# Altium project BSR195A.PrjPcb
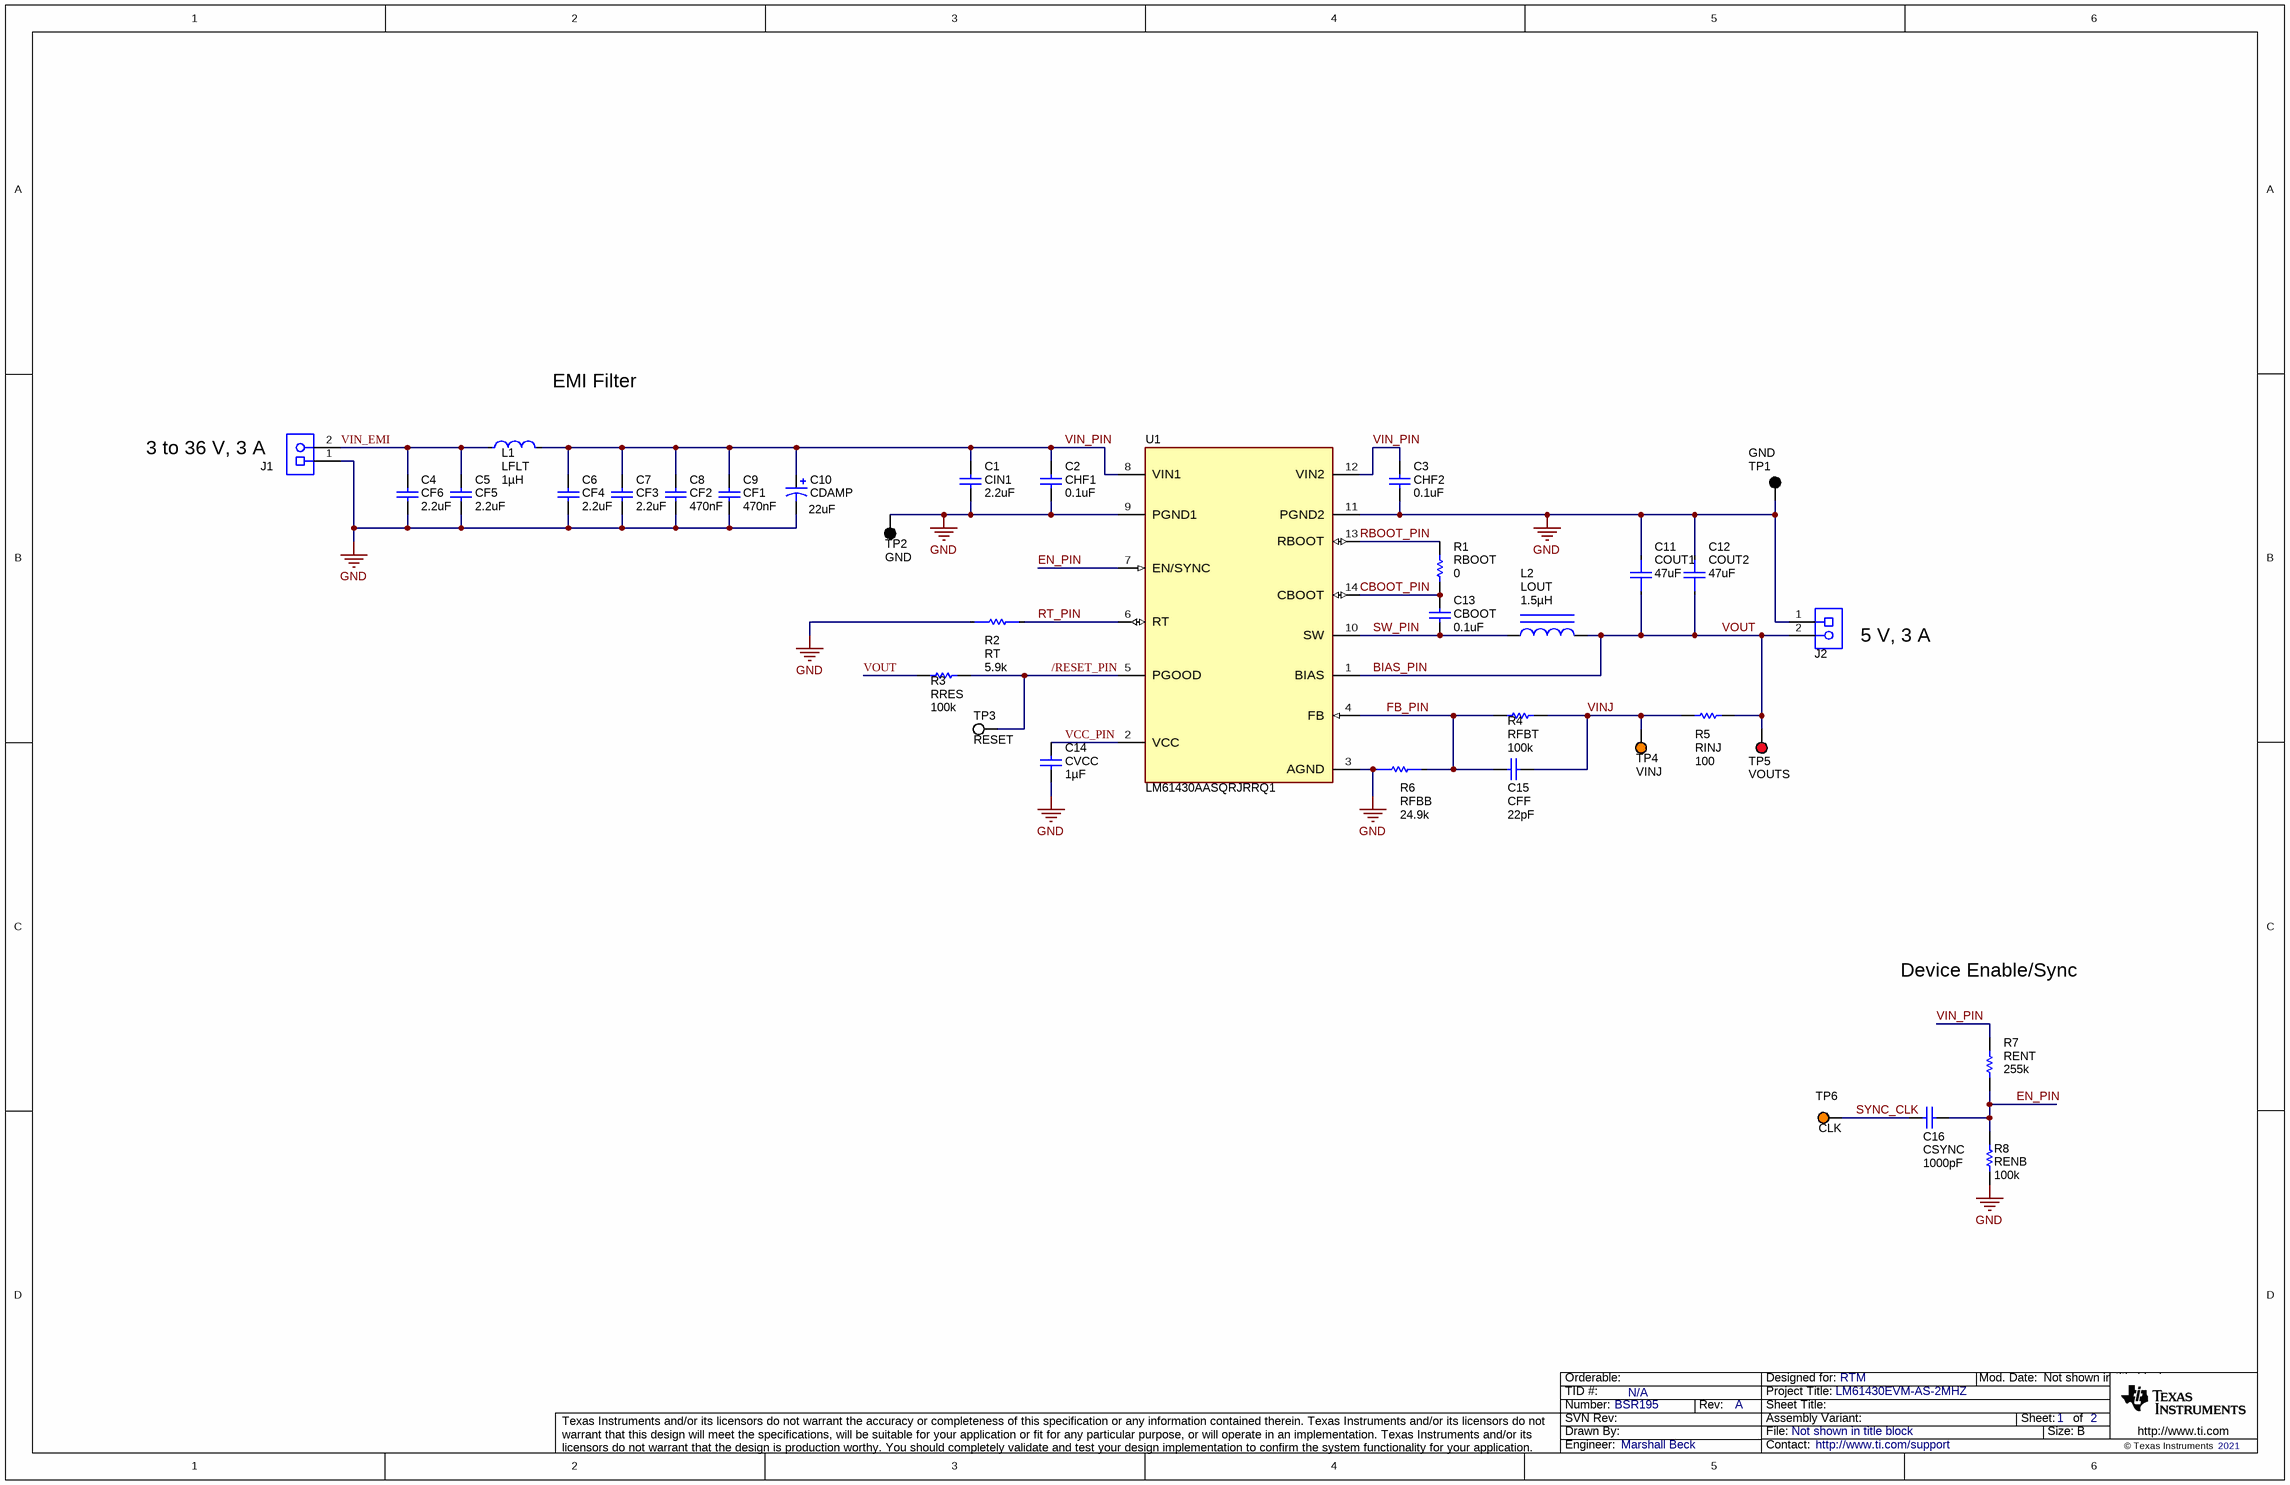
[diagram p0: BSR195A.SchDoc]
CopyrightYear: 2021; PCB_Layout: Marshall Beck; PCB_Rev: A; PRJ_Customer: RTM; PRJ_Engineer: Marshall Beck; PRJ_Number: BSR195; PRJ_Title: LM61430EVM-AS-2MHZ; SCH_Rev: A; TechSupport: http://www.ti.com/support; TID: N/A
2 sheets, 60 parts. Net scope: global (net labels, ports and power ports of the same name join across sheets).
Board file: BSR195A.PcbDoc
Sheets:
  BSR195A.SchDoc
  BSR195A_Hardware.SchDoc

## Sheet BSR195A.SchDoc
size 431 x 279 mm; Date: Not shown in title block; ApprovedBy: Not shown in title block; CheckedBy: Not shown in title block; Author: Not shown in title block; CompanyName: Not shown in title block; Engineer: Not shown in title block; Organization: Not shown in title block; Address1: Not shown in title block; Address2: Not shown in title block; Address3: Not shown in title block; Address4: Not shown in title block; DocumentNumber: 1; Revision: Use project parameter SCH_Rev; SheetNumber: 1; SheetTotal: 2; PageSetup: Record=PageOptions¦CenterHorizontal=True¦CenterVertical=True¦PrintScale=1.00¦XCorrection=1.00¦YCorrection=1.00¦PrintKind=0¦BorderSize=5000000¦LeftOffset=0¦BottomOffset=0¦Orientation=2¦PaperLength=1000¦PaperWidth=1000¦Scale=100¦PaperSource=15¦PrintQuality=600¦MediaType=1¦DitherType=10¦PaperKind=Letter¦PrintScaleMode=1

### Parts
C1  CIN1  ValueDisplayed: 2.2uF  [1206_180L]
C2  CHF1  ValueDisplayed: 0.1uF  [0402L]
C3  CHF2  ValueDisplayed: 0.1uF  [0402L]
C4  CF6  ValueDisplayed: 2.2uF  [1206_180L]
C5  CF5  ValueDisplayed: 2.2uF  [1206_180L]
C6  CF4  ValueDisplayed: 2.2uF  [1206_180L]
C7  CF3  ValueDisplayed: 2.2uF  [1206_180L]
C8  CF2  Cap_F: 470nF  [0805L]
C9  CF1  Cap_F: 470nF  [0805L]
C10  CDAMP  ValueDisplayed: 22uF  [SM_RADIAL_E]
C11  COUT1  ValueDisplayed: 47uF  [FP-CGA6P1X7S1A476M250AC_1210-MFG]
C12  COUT2  ValueDisplayed: 47uF  [FP-CGA6P1X7S1A476M250AC_1210-MFG]
C13  CBOOT  ValueDisplayed: 0.1uF  [0402L]
C14  CVCC  Cap_F: 1µF  [0603L]
C15  CFF  ValueDisplayed: 22pF  [0402L]
C16  CSYNC  ValueDisplayed: 1000pF  [0402L]
J1  691 101 710 002  [Wurth_691101710002]  (value not drawn)
J2  691 101 710 002  [Wurth_691101710002]  (value not drawn)
L1  LFLT  Ind_H: 1µH  [FP-74438336010_SMD2-MFG]
L2  LOUT  ValueDisplayed: 1.5µH  [WE-MAPI_4020]
R1  RBOOT  ValueDisplayed: 0  [0402L]
R2  RT  value 5.9k  [FP-ERJ-2RKF5901X_0402-IPC_B]
R3  RRES  ValueDisplayed: 100k  [0402L]
R4  RFBT  ValueDisplayed: 100k  [0402L]
R5  RINJ  ValueDisplayed: 100  [0603L]
R6  RFBB  value 24.9k  [FP-ERJ-2RKF2492X_0402-MFG]
R7  RENT  ValueDisplayed: 255k  [0402L]
R8  RENB  ValueDisplayed: 100k  [0402L]
TP1  GND  [Keystone5011]
TP2  GND  [Keystone5011]
TP3  RESET  [Keystone5012]
TP4  VINJ  [Keystone5013]
TP5  VOUTS  [Keystone5010]
TP6  CLK  [Keystone5013]
U1  LM61430AASQRJRRQ1  [RJR0014A-MFG]

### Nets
GND: C1.2 C2.2 C3.2 C4.2 C5.2 C6.2 C7.2 C8.2 C9.2 C10.2(-) C11.2 C12.2 C14.2 J1.1 J2.1 R2.1 R6.1 R8.1 TP1.1 TP2.1 U1.3(AGND) U1.9(PGND1) U1.11(PGND2)
/RESET_PIN: R3.2 TP3.1 U1.5(PGOOD)
BIAS_PIN: C11.1 C12.1 J2.2 L2.2 R3.1 R5.1 TP5.1 U1.1(BIAS)  [also labelled VOUT]
CBOOT_PIN: C13.1 R1.1 U1.14(CBOOT)
EN_PIN: C16.1 R7.1 R8.2 U1.7(EN/SYNC)
FB_PIN: C15.2 R4.1 R6.2 U1.4(FB)
RBOOT_PIN: R1.2 U1.13(RBOOT)
RT_PIN: R2.2 U1.6(RT)
SW_PIN: C13.2 L2.1 U1.10(SW)
SYNC_CLK: C16.2 TP6.1
VCC_PIN: C14.1 U1.2(VCC)
VIN_EMI: C4.1 C5.1 J1.2 L1.1
VIN_PIN: C1.1 C2.1 C3.1 C6.1 C7.1 C8.1 C9.1 C10.1(+) L1.2 R7.2 U1.8(VIN1) U1.12(VIN2)
VINJ: C15.1 R4.2 R5.2 TP4.1

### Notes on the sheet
- EMI Filter
- (near J1) 3 to 36 V, 3 A
- (near J2) 5 V, 3 A
- Device Enable/Sync

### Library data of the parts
C1 C4-C7 = CMP-0008814-2: CAP, CERM, 2.2 uF, 50 V, +/- 10%, X7R, AEC-Q200 Grade 1, 1206; Manufacturer: MuRata; PartNumber: GCM31CR71H225KA55L; TaMin_C: -55°C; Polarized: N; SizeAreaWB_mm2: 10.92; Value1: Unknown; U/M: EA; Value: 2.2uF; TaMax_C: 125°C; SizeZ_mm: 1.8; SizeX_mm: 3.2; SizeY_mm: 1.6; Cap_Case: 1206; Value2: 50V; SizeArea_mm2: 5.12; CompType: Capacitor; AEC Qualified: Y; Cap_F: 2.2µF; AEC Grade: 1; AEC Category: Q200
C2 C3 C13 = CMP-0006356-2: CAP, CERM, 0.1 uF, 50 V, +/- 10%, X7R, AEC-Q200 Grade 1, 0402; Manufacturer: MuRata; PartNumber: GCM155R71H104KE02D; TaMin_C: -55°C; Polarized: N; SizeAreaWB_mm2: 3; Value1: Unknown; U/M: EA; Value: 0.1uF; TaMax_C: 125°C; SizeZ_mm: 0.6; SizeX_mm: 1; SizeY_mm: 0.5; Cap_Case: 0402; Value2: 50V; CompType: Capacitor; AEC Qualified: Y; Cap_F: 100nF; AEC Category: Q200
C8 C9 = CMP-0008022-2: CAP, CERM, 0.47 uF, 50 V, +/- 10%, X7R, AEC-Q200 Grade 1, 0805; Manufacturer: MuRata; PartNumber: GCM21BR71H474KA55L; TaMin_C: -55°C; Polarized: N; SizeAreaWB_mm2: 6.75; Value1: Unknown; U/M: EA; Value: 0.47uF; TaMax_C: 125°C; SizeZ_mm: 1.45; SizeX_mm: 2; SizeY_mm: 1.25; Cap_Case: 0805; Value2: 50V; SizeArea_mm2: 2.5; CompType: Capacitor; AEC Qualified: Y; AEC Grade: 1; AEC Category: Q200
C10 = CMP-0011168-2: CAP, AL, 22 uF, 50 V, +/- 20%, 0.7 ohm, SMD; Manufacturer: Panasonic; PartNumber: EEE-FC1H220P; TaMin_C: -40°C; ESR_ohm: 7d; Polarized: Y; SizeAreaWB_mm2: 118.45; Value1: 0.7 ohm; U/M: EA; Value: 22uF; TaMax_C: 105°C; SizeZ_mm: 6.2; SizeX_mm: 9.5; SizeY_mm: 8.3; Cap_Case: E; Value2: 50V; SizeArea_mm2: 78.85; CompType: Capacitor; Cap_F: 22µF; IRMS_A: 1.2dA; AEC Category: Q200
C11 C12 = CMP-0092443-1: Multilayer Ceramic Capacitor 47uF 20% 10V 1210 T/R; PartNumber: CGA6P1X7S1A476M250AC; Manufacturer: TDK; AEC Grade: Grade 1; TempCo: 22%; Value: 47µF; AEC Qualified: Yes; Temperature Characteristic: X7S; SizeZ_mm: 2.8mm
C14 = CMP-0006831-4: CAP, CERM, 1 uF, 16 V, +/- 10%, X7R, 0603; Manufacturer: Wurth Elektronik; PartNumber: 885012206052; TaMin_C: -55°C; Polarized: N; SizeAreaWB_mm2: 4.68; Value1: Unknown; U/M: EA; Value: 1uF; TaMax_C: 125°C; SizeZ_mm: 1; SizeX_mm: 1.6; SizeY_mm: 0.8; Cap_Case: 0603; Value2: 16V; SizeArea_mm2: 1.28; CompType: Capacitor; AEC Category: Q200
C15 = CMP-0006311-2: CAP, CERM, 22 pF, 50 V, +/- 5%, C0G/NP0, AEC-Q200 Grade 1, 0402; Manufacturer: TDK; PartNumber: CGA2B2NP01H220J050BA; TaMin_C: -55°C; Polarized: N; SizeAreaWB_mm2: 3; Value1: Unknown; U/M: EA; Value: 22pF; TaMax_C: 125°C; SizeZ_mm: 0.6; SizeX_mm: 1; SizeY_mm: 0.5; Cap_Case: 0402; Value2: 50V; CompType: Capacitor; AEC Qualified: Y; AEC Category: Q200
C16 = CMP-0006314-2: CAP, CERM, 1000 pF, 50 V, +/- 10%, X7R, AEC-Q200 Grade 1, 0402; Manufacturer: TDK; PartNumber: CGA2B2X7R1H102K050BA; TaMin_C: -55°C; ESR_ohm: 2.25564; Polarized: N; SizeAreaWB_mm2: 3; Value1: 2.25564 ohm; U/M: EA; Value: 1000pF; TaMax_C: 125°C; SizeZ_mm: 0.6; SizeX_mm: 1; SizeY_mm: 0.5; Cap_Case: 0402; Value2: 50V; CompType: Capacitor; AEC Qualified: Y; Cap_F: 1nF; IRMS_A: 280.466mA; AEC Category: Q200
J1 J2 = CMP-0054828-1: Terminal Block, 5 mm, 2x1, Tin, TH; Manufacturer: Wurth Elektronik; CNHeader: FALSE; Green_Lifecycle: Active; Green_REACh: Passed; CT: TRUE
L1 = CMP-0087867-1: 1µH Shielded Molded Inductor 4A 32mOhm Max 2-SMD; Manufacturer: Wurth Electronics; PartNumber: 74438336010; SizeZ_mm: 2mm; Material: Metal Composite; Isat: 5A; Symbol Name: SYM-74438336010; DCR_ohm: 0.032; AEC Grade: Grade 1; AEC Qualified: Yes
L2 = CMP-0084012-1: Inductor, Shielded, Metal Composite, 1.5 µH, 5.8 A, 0.019 ohm, SMD; PartNumber: 74438356015; Manufacturer: Wurth Elektronik; SizeAreaWB_mm2: 26.01; Irms: 5.8A @ 40C rise; SizeArea_mm2: 16.81; AEC Qualified: N; AEC Category: Q200; Value: 1.5uH; SizeZ_mm: 2.1; Imax_A: 5.8A; SizeY_mm: 4.1; Isat: 7.8A @ 20% inductance drop; DCR_ohm: 0.019
R1 = CMP-0081856-1: RES, 0, 0%, 0.2 W, AEC-Q200 Grade 0, 0402; PartNumber: CRCW04020000Z0EDHP; Manufacturer: Vishay-Dale; SizeAreaWB_mm2: 3; SizeArea_mm2: 0.5; AEC Qualified: Y; AEC Category: Q200; Value: 0; SizeZ_mm: 0.6; Power_W: 200mW; VDC_V: 50V; Value2: 0.2W; CompType: Resistor; SizeX_mm: 1
R2 = CMP-0091636-1: 5.9 kOhms ±1% 0.1W, 1/10W Chip Resistor 0402 (1005 Metric) Automotive AEC-Q200 Thick Film; PartNumber: ERJ-2RKF5901X; Manufacturer: Panasonic; TempCo: 100ppm/°C; AEC Qualified: Yes; AEC Grade: Grade 0; VDC_V: 50V; Power_W: 100mW; SizeZ_mm: 0.4mm
R3 R4 R8 = CMP-0026768-2: RES, 100 k, 0.5%, 0.063 W, AEC-Q200 Grade 0, 0402; Manufacturer: Vishay-Dale; PartNumber: CRCW0402100KDHEDP; Power_W: 63mW; TempCo: 50 ppm/C; Value: 100k; EIA_Code: E192; SizeX_mm: 1; SizeY_mm: 0.5; SizeZ_mm: 0.6; Value2: 0.063W; CompType: Resistor; AEC Qualified: Y; VDC_V: 50V; AEC Category: Q200; AEC Grade: 0
R5 = CMP-0022736-4: RES, 100, 1%, 0.1 W, 0603; Manufacturer: Yageo; PartNumber: RC0603FR-07100RL; Power_W: 100mW; TempCo: 100 ppm/C; Value_Code: 100R; Value: 100; EIA_Code: E96; SizeX_mm: 1.6; SizeY_mm: 0.8; SizeZ_mm: 1; Value2: 0.1W; SizeArea_mm2: 1.28; CompType: Resistor; AEC Qualified: N; VDC_V: 75V; AEC Category: Q200; SizeAreaWB_mm2: 4.68
R6 = CMP-0091635-1: 24.9 kOhms ±1% 0.1W, 1/10W Chip Resistor 0402 (1005 Metric) Automotive AEC-Q200 Thick Film; Part Number: ERJ-2RKF2492X; Manufacturer: Panasonic; AEC Grade: Grade 0; AEC Qualified: Yes; VDC_V: 50V; Power_W: 100mW; SizeZ_mm: 0.4mm; TempCo: 100ppm/°C
R7 = CMP-0026199-2: RES, 255 k, 1%, 0.063 W, AEC-Q200 Grade 0, 0402; Manufacturer: Vishay-Dale; PartNumber: CRCW0402255KFKED; Power_W: 63mW; TempCo: 100 ppm/C; Value: 255k; EIA_Code: E96; SizeX_mm: 1; SizeY_mm: 0.5; SizeZ_mm: 0.6; Value2: 0.063W; CompType: Resistor; AEC Qualified: Y; VDC_V: 50V; AEC Category: Q200; AEC Grade: 0
TP1 TP2 = CMP-0055148-1: Test Point, Multipurpose, Black, TH; Manufacturer: Keystone; PartNumber: 5011; CNHeader: FALSE; Green_Lifecycle: Active; Green_REACh: Passed; ContactFinish: Silver; CT: TRUE
TP3 = CMP-0055149-1: Test Point, Multipurpose, White, TH; Manufacturer: Keystone; PartNumber: 5012; CNHeader: FALSE; Green_Lifecycle: Active; Green_REACh: Passed; ContactFinish: Silver; CT: TRUE
TP4 TP6 = CMP-0055150-1: Test Point, Multipurpose, Orange, TH; Manufacturer: Keystone; PartNumber: 5013; CNHeader: FALSE; Green_Lifecycle: Active; Green_REACh: Passed; ContactFinish: Silver; CT: TRUE
TP5 = CMP-0055147-1: Test Point, Multipurpose, Red, TH; Manufacturer: Keystone; PartNumber: 5010; CNHeader: FALSE; Green_Lifecycle: Active; Green_REACh: Passed; ContactFinish: Silver; CT: TRUE
U1 = CMP-0092866-1: 3-V to 36-V, Low EMI Synchronous Step-Down Converter; Manufacturer: Texas Instruments; AEC Grade: Grade 1; Output Type: AdjustableProgrammable; Switching Frequency: 200-2200kHz; Output Voltage: 1-34.2V; Max Duty Cycle: 98%; Number Of Outputs: 1; Max Supply Voltage: 36V; SizeZ_mm: 1mm; Min Supply Voltage: 3V; Standoff Height: 0mm; TJmax_C: +150°C; Switching Topology: Buck; AEC Qualified: Yes; Nominal Supply Current: 9uA

## Sheet BSR195A_Hardware.SchDoc
size 431 x 279 mm; Date: Not shown in title block; ApprovedBy: Not shown in title block; CheckedBy: Not shown in title block; Author: Not shown in title block; CompanyName: Not shown in title block; Engineer: Not shown in title block; Organization: Not shown in title block; Address1: Not shown in title block; Address2: Not shown in title block; Address3: Not shown in title block; Address4: Not shown in title block; DocumentNumber: 1; Revision: Use project parameter SCH_Rev; SheetNumber: 2; SheetTotal: 2; PageSetup: Record=PageOptions¦CenterHorizontal=True¦CenterVertical=True¦PrintScale=1.00¦XCorrection=1.00¦YCorrection=1.00¦PrintKind=0¦BorderSize=5000000¦LeftOffset=0¦BottomOffset=0¦Orientation=2¦PaperLength=1000¦PaperWidth=1000¦Scale=100¦PaperSource=15¦PrintQuality=600¦MediaType=1¦DitherType=10¦PaperKind=Letter¦PrintScaleMode=1
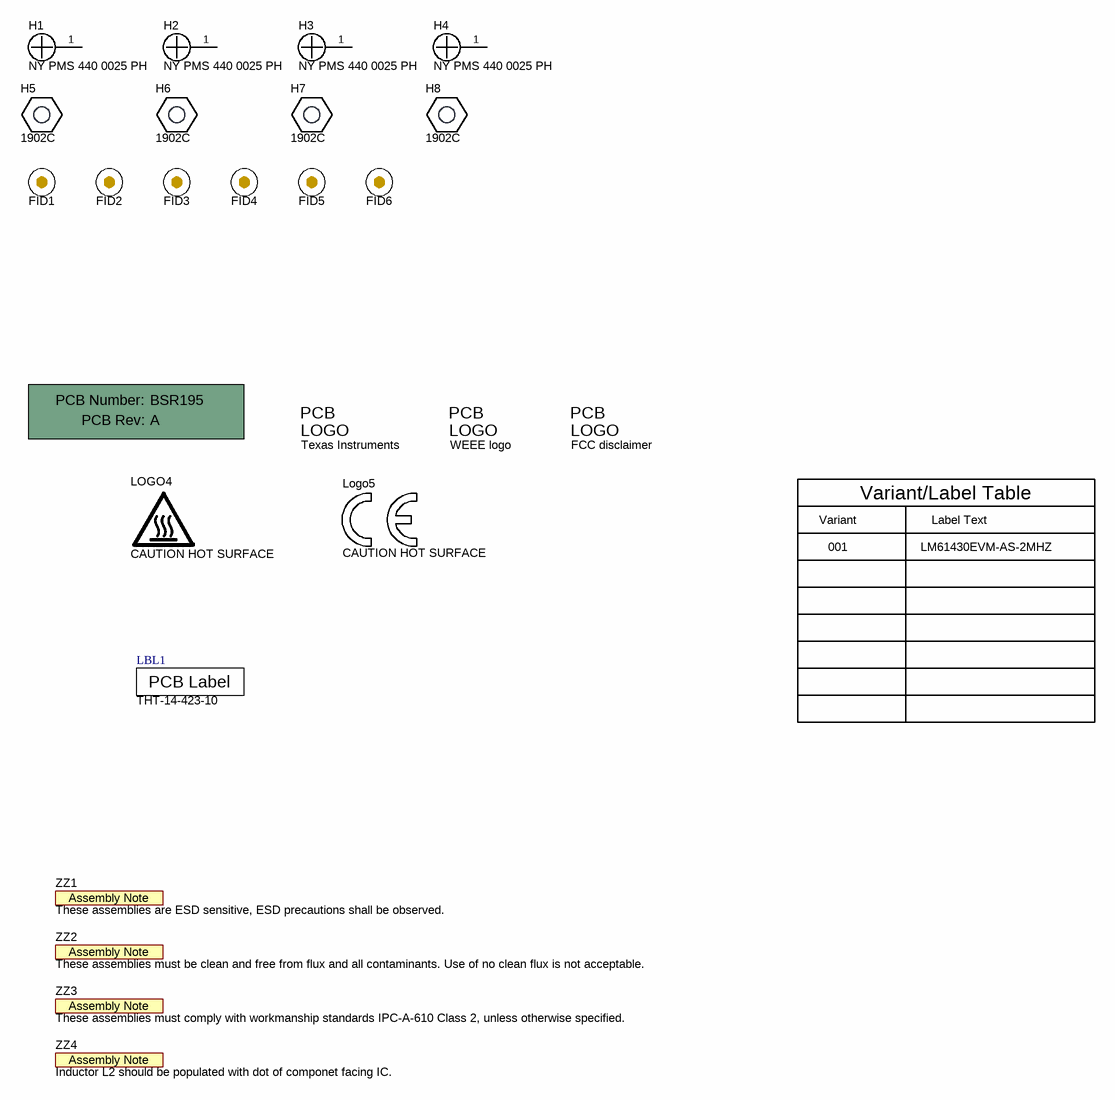
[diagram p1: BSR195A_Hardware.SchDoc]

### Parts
!PCB1  Printed Circuit Board  (value not drawn)  (mechanical)
FID1  Fiducial  [Fiducial10-20]  (value not drawn)
FID2  Fiducial  [Fiducial10-20]  (value not drawn)
FID3  Fiducial  [Fiducial10-20]  (value not drawn)
FID4  Fiducial  [Fiducial10-20]  (value not drawn)
FID5  Fiducial  [Fiducial10-20]  (value not drawn)
FID6  Fiducial  [Fiducial10-20]  (value not drawn)
H1  NY PMS 440 0025 PH  [NY PMS 440 0025 PH]
H2  NY PMS 440 0025 PH  [NY PMS 440 0025 PH]
H3  NY PMS 440 0025 PH  [NY PMS 440 0025 PH]
H4  NY PMS 440 0025 PH  [NY PMS 440 0025 PH]
H5  1902C  [Keystone_1902C]
H6  1902C  [Keystone_1902C]
H7  1902C  [Keystone_1902C]
H8  1902C  [Keystone_1902C]
LBL1  THT-14-423-10  [Label_650x200]
Logo1  Texas Instruments  [TI_Stacked_Overlay_Small]  (no BOM)
Logo2  WEEE logo  [WEEE_Minimum]  (no BOM)
Logo3  FCC disclaimer  [FCC_disclaimer]  (no BOM)
LOGO4  CAUTION HOT SURFACE  [IEC_HotSurface_Small]  (no BOM)
Logo5  CAUTION HOT SURFACE  [CE_Mark_5mm]  (no BOM)
ZZ1  These assemblies are ESD sensitive, ESD precautions shall be observed.  [AssemblyNote]  (no BOM)
ZZ2  These assemblies must be clean and free from flux and all contaminants. Use of no clean flux is not acceptable.  [AssemblyNote]  (no BOM)
ZZ3  These assemblies must comply with workmanship standards IPC-A-610 Class 2, unless otherwise specified.  [AssemblyNote]  (no BOM)
ZZ4  Inductor L2 should be populated with dot of componet facing IC.  [AssemblyNote]  (no BOM)

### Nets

Not connected (* = marked no-connect by the designer): H1 1; H2 1; H3 1; H4 1

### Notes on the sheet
- Variant
- Variant/Label Table
- Label Text
- 001
- LM61430EVM-AS-2MHZ

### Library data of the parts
!PCB1 = CMP-0003618-2: Manufacturer: Any; PartNumber: BSR195; CompType: PCB
FID1-FID6 = CMP-0077181-1: Fiducial mark.  There is nothing to buy or mount.
H1-H4 = CMP-0003617-1: Machine Screw, Round, #4-40 x 1/4, Nylon, Philips panhead; Manufacturer: B&F Fastener Supply; CompType: Hardware
H5-H8 = CMP-0003610-1: Manufacturer: Keystone; CompType: Hardware
LBL1 = CMP-0003625-1: Manufacturer: Brady
Logo1 = CMP-0074838-1: Texas Instrument Corporate Signature; SymbolCreator: a0412235; Lib Reference: TI_Logo; Library Reference: Logo
Logo2 = CMP-0074769-1
Logo3 = CMP-0074847-1: FCC_disclaimer; Library Reference: Logo
LOGO4 = CMP-0074837-1: IEC 61010-1 Hot Surface Warning; Library Reference: IEC_HotSurface; SymbolCreator: a0412235
Logo5 = CMP-0074844-1: CE Mark; SymbolCreator: a0412235
ZZ1 = CMP-0077236-1
ZZ2 = CMP-0077237-1
ZZ3 = CMP-0077238-1
ZZ4 = CMP-0077238-1: These assemblies must comply with workmanship standards IPC-A-610 Class 2, unless otherwise specified.

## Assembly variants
001: not fitted C12 R8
